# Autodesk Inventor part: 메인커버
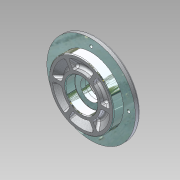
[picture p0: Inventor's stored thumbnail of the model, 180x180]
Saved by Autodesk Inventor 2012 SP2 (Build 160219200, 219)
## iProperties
Manager: KYOUNG IL JANG
Company: 한국ATC센터
Created: 2012-10
Part Number: 메인커버
Document SubType Name: Modeling
Density: 1 g/cm^3
Checked By: KYOUNG IL JANG
Vendor: CBT Solutions
Designer: KYOUNG IL JANG
Material: 기본값
Author: KYOUNG IL JANG
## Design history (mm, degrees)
sketch "스케치1"
  geometry: L1 (0, 0)-(0, 28.5); L2 (0, 0)-(28.5, 0); L3 (28.5, 0)-(28.5, 4.726); L4 (28.5, 8)-(31.774, 8); L5 (32.966, 8)-(33.879, 7.234); L6 (42.5, 0)-(47.5, 0); L7 (47.5, 0)-(47.5, 14.5); L8 (47.5, 14.5)-(65, 14.5); L9 (65, 14.5)-(65, 22.5); L10 (65, 22.5)-(33.464, 22.5); L11 (33.464, 22.5)-(30, 28.5); L12 (30, 28.5)-(0, 28.5); L13 (28.5, 4.726)-(28.5, 8); L14 (31.774, 8)-(32.966, 8); L15 (33.879, 7.234)-(42.5, 0); L16 (23.5, 0)-(23.5, 14); L17 (23.5, 14)-(15, 14); L18 (15, 14)-(15, 20.5); L19 (15, 20.5)-(17.5, 20.5); L20 (17.5, 20.5)-(17.5, 28.5); A1 r 3.274 centre (31.774, 4.726) between (33.879, 7.234) and (28.5, 4.726)
  constraints: 40 end point, 11 parallel, 6 perpendicular, 6 tangent, 3 point on circle, 2 collinear, 2 point on line, 1 centre point, 1 vertical
  dimensions: "d1" = 130 diameter of L9 L1; "d2" = 95 diameter of L7 L1; "d3" = 57 diameter of L3 L1; "d4" = 5 distance of L6.start L6.end; "d5" = 14.5 distance between parallel lines of L8 L6; "d6" = 8 distance of L8.end L9.end; "d7" = 6 distance between parallel lines of L10 L12; "d8" = 8 distance of L2.end L4.start; "d9" = 140 deg angle of L6 L5; "d10" = 47 diameter of L16 L1; "d11" = 14 distance of L16.start L16.end; "d12" = 35 diameter of L20 L1; "d13" = 8 distance of L19.end L20.end; "d14" = 30 diameter of L18 L1; "d15" = 120 deg angle of L10 L11; "d16" = 60 diameter of L11.end L1
revolve "회전1" sketch "스케치1" stored, may be unused: angle "d17" = 90 deg
sketch "스케치2"
  geometry: L1 (28.5, 0)-(42.5, 0); 3 further points
  constraints: 2 end point, 2 horizontal alignment, 1 horizontal, 1 point on line, 2 other
feature "리브1" sketch "스케치2" dims "d18" = 5, "d19" = 1, "d20" = 0
fillet "모깎기1" dims "d21" = 3
fillet "모깎기2" dims "d25" = 3, "d26" = 0.3
chamfer "모따기1" distance "d27" = 1; stored, may be unused: second distance "d28" = 2, angle "d29" = 45 deg
sketch "스케치3"
  geometry: C1 r 2.067 at (55, 0) reference; C2 r 2.067 at (0, -55) reference; C3 r 2.067 at (-55, 0) reference; C4 r 2.067 at (0, 55) reference; 1 further point
hole "구멍1" sketch "스케치3" at (0, 55), (-55, 0), (0, -55), (55, 0) diameter "d30" = 4.5; stored, may be unused: countersink angle "d34" = 90 deg, drill point angle "d36" = 118 deg; dims "d31" = 6, "d32" = 8, "d33" = 4.4, "d35" = 8
node "솔리드1"
pattern_circular "원형 패턴1" dims angle "d23" = 360 deg
node "참조1"
node "참조2"
node "참조3"
node "참조4"
